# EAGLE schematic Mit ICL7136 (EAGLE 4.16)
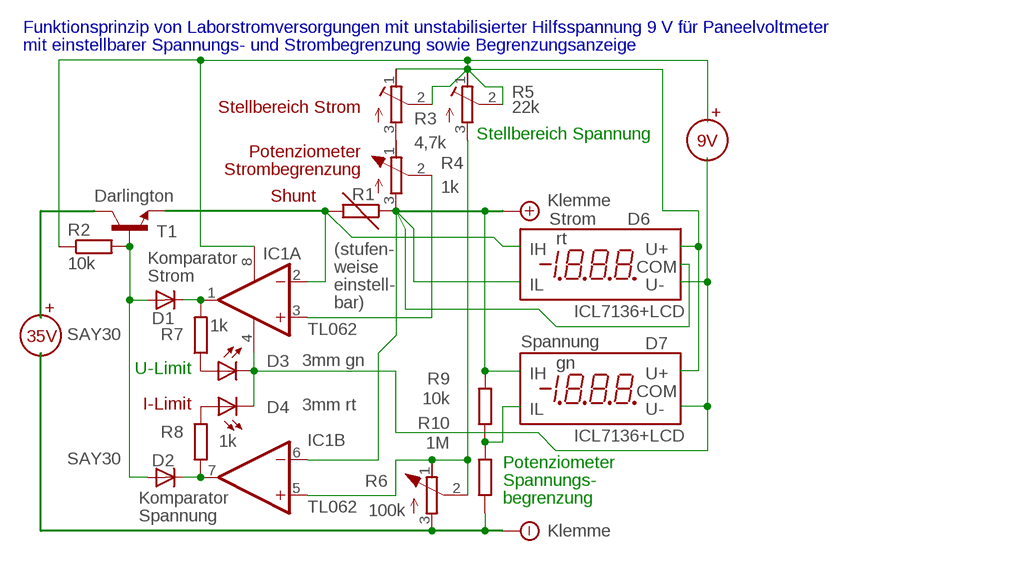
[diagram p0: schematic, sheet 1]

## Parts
D1  SAY30  DIODE-D-10  [D-10]
D2  SAY30  DIODE-D-10  [D-10]
D3  3mm gn  LED5MM  [LED5MM]
D4  3mm rt  LED5MM  [LED5MM]
IC1  TL062  TL082P  [DIL08]
R1  R-EU_0207/10  [0207/10]
R2  10k  R-EU_0207/10  [0207/10]
R3  4,7k  R-TRIMMT93YB  [RTRIMT93YB]
R4  1k  R-TRIMMT93YB  [RTRIMT93YB]
R5  22k  R-TRIMMT93YB  [RTRIMT93YB]
R6  100k  R-TRIMMT93YB  [RTRIMT93YB]
R7  1k  R-EU_0207/10  [0207/10]
R8  1k  R-EU_0207/10  [0207/10]
R9  10k  R-EU_0207/10  [0207/10]
R10  1M  R-EU_0207/10  [0207/10]
T1  -NPN-TO3/  [TO3]

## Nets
00: IC1.6(B:-IN) R1.1 R4.3(E) R9.2 ; supply symbol labelled Klemme
5P: IC1.8(P:V+) R2.1 R3.1(A) R3.2(S) R5.1(A) R5.2(S)
+UB: T1.C
-UB: R6.3(E) R10.1 ; supply symbol labelled Klemme
N$1: D1.A D2.A R2.2 T1.B
N$2: IC1.3(A:+IN) R4.2(S)
N$3: D3.A R7.1
N$4: D4.A R8.2
N$5: R9.1 R10.2
N$6: R3.3(E) R4.1(A)
N$8: D2.C IC1.7(B:OUT) R8.1
N$9: D1.C IC1.1(A:OUT) R7.2
N$11: D3.K(C) D4.K(C) IC1.4(P:V-)
N$15: IC1.2(A:-IN) R1.2 T1.E
N$85: IC1.5(B:+IN) R5.3(E) R6.1(A) R6.2(S)

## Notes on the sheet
- Funktionsprinzip von Laborstromversorgungen mit unstabilisierter Hilfsspannung 9 V für Paneelvoltmeter
- mit einstellbarer Spannungs- und Strombegrenzung sowie Begrenzungsanzeige
- Stellbereich Strom
- +
- Stellbereich Spannung
- 9V
- Potenziometer
- Strombegrenzung
- Darlington | Shunt
- Strom | D6
- rt
- (stufen- | IH | U+
- Komparator
- weise | COM
- Strom
- einstell- | IL | U-
- bar)
- + | ICL7136+LCD
- 35V
- Spannung | D7
- U-Limit
- gn
- IH | U+
- I-Limit | COM
- IL | U-
- ICL7136+LCD
- Potenziometer
- Spannungs-
- Komparator | begrenzung
- Spannung

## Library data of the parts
D1 D2 = diode:DIODE-: DIODE
D3 D4 = led:LED: LED
IC1 = linear:TL082: OP AMP
R1 R2 R7-R10 = rcl:R-EU_: RESISTOR, European symbol
R3-R6 = rcl:R-TRIMM: Trimm resistor
T1 = transistor:*-NPN-: NPN Transistror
